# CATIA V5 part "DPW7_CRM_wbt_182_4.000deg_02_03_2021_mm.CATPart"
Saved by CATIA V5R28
Part number: DPW7_CRM_wbt_182_4.006deg_02_03_2021
Bounding box of the stored display mesh (mm): x 2349.5 to 66711.891, y 0 to 29465.711, z 2310.119 to 8715.756
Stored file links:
  Z:\Scratch\04_CAD_Allgemein\Flight2Jig\Output\DPW-7\CATPart\DPW7_CRM_wbt_182_4.006deg_02_03_2021.CATPart
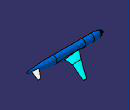
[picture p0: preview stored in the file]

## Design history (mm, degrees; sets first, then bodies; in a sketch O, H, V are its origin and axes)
Set1
  DatumSurface1 "Clean_Wing"
  DatumSurface2 "Fuselage"
  DatumSurface3 "HTP"
  DatumSurface4 "Symmetry"
  DatumSurface5 "Farfield"
Body1 (main body)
